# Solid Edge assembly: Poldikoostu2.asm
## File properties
Author: Türk
Template: Iso Assembly.asm
Last saved by: Türk
Revision: 2
Application: Solid Edge
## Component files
Polt69,5x20.par
Mutter.par
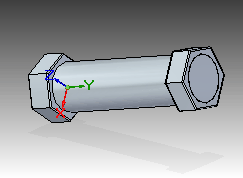
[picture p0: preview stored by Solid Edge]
